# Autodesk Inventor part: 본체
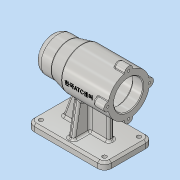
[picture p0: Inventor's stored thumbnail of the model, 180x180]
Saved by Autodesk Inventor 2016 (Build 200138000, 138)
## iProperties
Created: 2019-07
Part Number: 본체
Material: 알루미늄 6061
Document SubType Name: Modeling
Designer: MIRAE
Density: 2.7 g/cm^3
Appearance: 알루미늄 - 평지
Mass: 644.389 g
Surface Area: 654.079 cm^2
Volume: 238.663 cm^3
Author: MIRAE
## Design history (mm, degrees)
sketch "스케치1"
  geometry: L1 (-56, 0)-(56, 0); L2 (56, 30)-(56, 21); L3 (56, 21)-(41, 21); L4 (56, 30)-(-11, 30); L5 (41, 21)-(41, 24); L6 (41, 24)-(-13, 24); L7 (-13, 24)-(-13, 21); L8 (-13, 21)-(-25, 21); L9 (-25, 21)-(-25, 17.5); L10 (-25, 17.5)-(-43, 17.5); L11 (-43, 17.5)-(-43, 16); L12 (-43, 16)-(-47, 16); L13 (-47, 16)-(-47, 10.5); L14 (-47, 10.5)-(-50, 10.5); L15 (-50, 10.5)-(-50, 0); L16 (-56, 0)-(-56, 25); L17 (-56, 25)-(-31, 25); L18 (-31, 25)-(-11, 30); 1 further point
  constraints: 36 end point, 7 vertical, 6 horizontal, 4 perpendicular, 1 midpoint, 1 point on line
  dimensions: "d0" = 112 distance of L1.start L1.end; "d1" = 56 distance of point (0, 0) L1.end; "d3" = 42 diameter of L3 L1; "d4" = 60 diameter of L4 L1; "d5" = 15 distance of L2.end L3.end; "d6" = 54 distance of L5.end L6.end; "d7" = 48 diameter of L6 L1; "d8" = 42 diameter of L8 L1; "d9" = 12 distance of L7.end L8.end; "d10" = 35 diameter of L10 L1; "d11" = 18 distance of L9.end L10.end; "d12" = 4 distance of L11.end L12.end; "d13" = 32 diameter of L12 L1; "d14" = 3 distance of L13.end L14.end; "d15" = 21 diameter of L14 L1; "d16" = 50 diameter of L17 L1; "d17" = 25 distance of L16.end L17.end; "d18" = 45 distance from line of L4.end L16
revolve "회전1" sketch "스케치1" stored, may be unused: angle "d19" = 90 deg
sketch "스케치2"
  geometry: L1 (-56, -70)-(56, -70); L2 (56, -70)-(56, -80); L3 (56, -80)-(-56, -80); L4 (-56, -80)-(-56, -70); L5 (-11, -30)-(-11, 30) reference; L6 (56, -30)-(56, 30) reference; 1 further point
  constraints: 8 end point, 2 parallel, 1 horizontal, 1 perpendicular, 1 vertical alignment
  dimensions: "d20" = 80 distance from line of point (0, 0) L3; "d21" = 10 distance of L1.end L2.end; "d22" = 112 distance of L2.end L3.end
extrude "돌출1" join sketch "스케치2" stored distance "d23" = 70; taper "d24" = 0 deg
sketch "스케치3"
  geometry: L1 (20, 39)-(87, 39); L2 (87, 39)-(87, 31); L3 (87, 31)-(20, 31); L4 (20, 31)-(20, 39); L5 (112, 0)-(112, 70) reference; L6 (0, 0)-(0, 70) reference; 2 further points
  constraints: 8 end point, 2 parallel, 1 horizontal, 1 horizontal alignment, 1 midpoint, 1 perpendicular
  dimensions: "d26" = 8 distance of L1.end L2.end; "d27" = 25 distance between parallel lines of L5 L2; "d28" = 20 distance between parallel lines of L6 L4
extrude "돌출2" join sketch "스케치3" stored distance "d29" = 70; taper "d30" = 0 deg
feature "면 기울기1" dims angle "d31" = 20 deg
sketch "스케치4"
  geometry: L1 (-22.666, -19.654)-(-70, -28); L2 (-70, -35)-(-70, 35) reference; A1 r 30 centre (0, 0) between (-29.732, -4) and (-29.732, 4) reference; 1 further point
  constraints: 2 end point, 1 point on circle, 1 point on line
  dimensions: "d32" = 100 deg angle of L2 L1; "d33" = 7 distance of L1.end L2.start
feature "리브1" sketch "스케치4" dims "d34" = 1, "d35" = 8, "d36" = 0, "d37" = 0, "d38" = 1, "d39" = 1
fillet "모깎기1" dims "d40" = 10
sketch "스케치5"
  geometry: L1 (-10, 60)-(-10, 10) reference; L2 (92, 0)-(0, 0) reference; L3 (102, 10)-(102, 60) reference; L4 (0, 70)-(92, 70) reference; L5 (42, 63)-(50, 63) reference; L6 (50, 63)-(50, 39) reference; L7 (50, 39)-(77, 39) reference; L8 (77, 39)-(77, 31) reference; L9 (77, 31)-(50, 31) reference; L10 (50, 31)-(50, 7) reference; L11 (50, 7)-(42, 7) reference; L12 (42, 7)-(42, 31) reference; L13 (42, 31)-(10, 31) reference; L14 (10, 31)-(10, 39) reference; L15 (10, 39)-(42, 39) reference; L16 (42, 39)-(42, 63) reference; A1 r 10 centre (0, 60) between (0, 70) and (-10, 60) reference; A2 r 10 centre (0, 10) between (-10, 10) and (0, 0) reference; A3 r 10 centre (92, 10) between (92, 0) and (102, 10) reference; A4 r 10 centre (92, 60) between (102, 60) and (92, 70) reference; 1 further point
hole "구멍1" sketch "스케치5" at (0, 10), (0, 60), (92, 60), (92, 10) diameter "d41" = 6; stored, may be unused: countersink angle "d45" = 90 deg, drill point angle "d47" = 0 deg; dims "d42" = 6, "d43" = 4, "d44" = 2, "d46" = 8
fillet "모깎기2" dims "d48" = 10
sketch "스케치6"
  geometry: A1 r 30 centre (0, 0) between (0, 30) and (-5.97, 29.4) reference; A2 r 6 centre (0, 30) between (5.97, 29.4) and (-5.97, 29.4); 1 further point
  constraints: 5 point on circle, 1 centre point, 1 vertical alignment
  dimensions: "d49" = 6 radius of A2
extrude "돌출3" join sketch "스케치6" distance "d50" = 16; taper "d51" = 0 deg
hole "구멍2" diameter "d54" = 3.242; stored, may be unused: countersink angle "d58" = 90 deg, drill point angle "d60" = 120 deg; dims "d52" = 10, "d53" = 10, "d55" = 8, "d56" = 4, "d57" = 2, "d59" = 11
chamfer "모따기1" distance "d64" = 1; stored, may be unused: second distance "d65" = 2, angle "d66" = 45 deg
fillet "모깎기3" dims "d67" = 0.3
fillet "모깎기4" dims "d68" = 3
fillet "모깎기5" dims "d69" = 3
fillet "모깎기6" dims "d70" = 3
fillet "모깎기7" dims "d71" = 3
fillet "모깎기8" dims "d72" = 1
node "작업 평면1"
sketch "스케치7"
  geometry: L1 (33.5, 6.771)-(33.5, 29.226) reference; 2 further points
  constraints: 1 horizontal alignment, 1 other
  dimensions: "d73" = 42 distance from line of L1 point (-8.5, 0)
feature "엠보싱1" sketch "스케치7" dims "d0" = 112, "d1" = 56, "d3" = 42, "d4" = 60, "d5" = 15, "d6" = 54, "d7" = 48, "d8" = 42, "d9" = 12, "d10" = 35, "d11" = 18, "d12" = 4, "d13" = 32, "d14" = 3, "d15" = 21, "d16" = 50, "d17" = 25, "d18" = 45, "d74" = 0.5, "d75" = 0
chamfer "모따기2" distance "d76" = 3; stored, may be unused: second distance "d77" = 2, angle "d78" = 45 deg
node "솔리드1"
mirror "대칭1"
pattern_circular "원형 패턴1" dims angle "d62" = 360 deg
node "투영된 루프1"
node "투영된 루프2"
